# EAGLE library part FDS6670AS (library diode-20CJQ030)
Fairchild's FDS6670AS 30V N-Channel PowerTrench® SyncFET General Description: The FDS6670AS is designed to replace a single SO-8 MOSFET and Schottky diode in synchronous DC:DC power supplies. This 30V MOSFET is designed to maximize power conversion efficiency, providing a low RDS(ON) and low gate charge. The FDS6670AS includes an integrated Schottky diode using Fairchild's monolithic SyncFET technology. Applications: DC/DC converter Low side notebook Features: 13.5 A, 30 V. RDS(ON) max= 9.0 mOhm @ VGS = 10 V RDS(ON) max= 11.5 mOhm @ VGS = 4.5 V Includes SyncFET Schottky body diode Low gate charge (27nC typical) High performance trench technology for extremely low RDS(ON) and fast switching High power and current handling capability Please send any comments to: messi@users.sourceforge.net
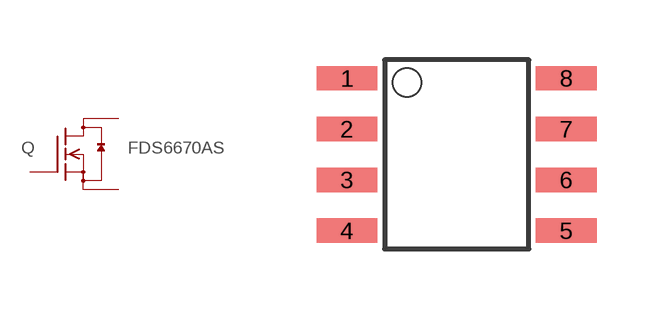
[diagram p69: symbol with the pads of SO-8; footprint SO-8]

Designator prefix Q

## FDS6670AS  [SO-8]
1  S  pas
2  S  pas
3  S  pas
4  G  pas
5  D  pas
6  D  pas
7  D  pas
8  D  pas

## Footprint SO-8 (pad centres in mm)
small outline
smd 1.524 x 0.61: 1 -2.743,1.27; 2 -2.743,0; 3 -2.743,-1.27; 4 -2.743,-2.54; 5 2.743,-2.54; 6 2.743,-1.27; 7 2.743,0; 8 2.743,1.27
